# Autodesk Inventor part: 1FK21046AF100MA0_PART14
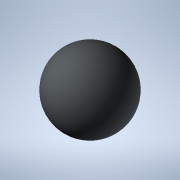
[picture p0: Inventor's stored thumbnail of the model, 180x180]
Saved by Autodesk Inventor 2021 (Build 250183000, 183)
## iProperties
Created: 2025-04
Part Number: 1FK21046AF100MA0_PART14
Material: Generic
Catalog Web Link: www.3dfindit.com
Description: -Servo synchronous motor
Document SubType Name: Modeling
Designer: psAdmin
Mass: 0.137258 g
Surface Area: 1.2868 cm^2
Volume: 0.137258 cm^3
Density: 1 g/cm^3
Appearance: PSOLRGB-212-217-219
Category: PARTsolutions
Title: 1FK21046AF100MA0_PART14
Author: Cadenas PARTsolutions
Comments: Servo synchronous motor
Sending System: PARTsolutions
Preprocessor: ST-DEVELOPER v19.3
PSOL_IDENT_0: {$CADENAS_DATA/23d-libs/siemens_ag/_cat_/4f/2b/1fk21046af100ma0.prj},216 {VTYP=3D},{NB=1FK21046AF100
PSOL_IDENT_1: MA0_PART14},{LINA=1FK21046AF100MA0_PART14},{NN=1FK21046AF100MA0_PART14},{NOPRJ=TRUE},{DATE=19.08.202
PSOL_IDENT_2: 5 14:00:37},{GEOMDATE=30.07.2025 02:01:06},{VERSION=},{LINEID=10},{WBVAR=},{WBNUMERIC=}  {NB=1FK2104
PSOL_IDENT_3: 6AF100MA0_PART14},{LINA=1FK21046AF100MA0_PART14},{KT=DUMMY},{PREVIEW=../../../_pool_/cb/72/p_d211_xx
PSOL_IDENT_4: _00434j.png},{DESCSHORT=SIMOTICS S-1FK2 HD, SINAMICS S210 3AC 400V-480V, 3.2 Nm, 3000 rpm},{DESCLONG=
PSOL_IDENT_5: SIMOTICS S-1FK2 HD servo motor M0=3.2 Nm; PN = 1 kW at nN=3000 rpm (380-480 V); PN = 0.5 kW at nN=15
PSOL_IDENT_6: 00 rpm (200-240 V); with holding brake; degree of protection IP64; cylindrical shaft D19x40mm; absol
PSOL_IDENT_7: ute encoder 22-bit + 12-bit multiturn (encoder AM22DQC); with OCC interface; plug size M17, rotatabl
PSOL_IDENT_8: e; SIMOTICS S-1FK2 servomotorfor a wide range of uses in industrial environments. SIMOTICS S‑1FK2 se
PSOL_IDENT_9: rvomotors are compact synchronous motors with a high dynamic performance that set themselves apart a
PSOL_IDENT_10: s a result of their high power density, degree of protection and overload capability. The motors are
PSOL_IDENT_11: available in two variants: as High Dynamic variant (highest dynamic performance as a result of the
PSOL_IDENT_12: low intrinsic moment of inertia for applications demanding a high dynamic performance with low moved
PSOL_IDENT_13: masses) - and as Compact variant (precise and stable closed-loop control for medium up to large mov
PSOL_IDENT_14: ed masses as a result of a medium intrinsic moment of inertia). SIMOTICSS‑1FK2 servomotors fully exp
PSOL_IDENT_15: loit their strengths in a system with the SINAMICSS210 frequency converter and simple connection usi
PSOL_IDENT_16: ng the one cable connection (OCC). Advantages include the short control and positioning times, fast
PSOL_IDENT_17: and precise correction of disturbing quantities as well as stable control with a high dynamic perfor
PSOL_IDENT_18: mance. The servo motors can be configured to address a wide range of requirements. For example with
PSOL_IDENT_19: and without holding brake, IP64 or IP65 degree of protection, singleturn or multiturn absolute encod
PSOL_IDENT_20: ers - to name just a few. Further, the servomotors are available in different shaft heights extendin
PSOL_IDENT_21: g from 20 to 100. A shaft sealing ring is available to achieve an IP65 degree of protection and for
PSOL_IDENT_22: subsequent mounting at the motor or as spare part. SIMOTICS - the optimum motor for each and every m
PSOL_IDENT_23: otion control application.},{INTNO=195125049673},{SUPPLIERALTNO=1FK2104-6AF10-0MA0},{MANUID=1FK21046
PSOL_IDENT_24: AF100MA0},{MANUNAME=Siemens},{MANUTYPEDESC=Synchronous motor 1FK2-HD 3.2 NM},{AAU732=SIMOTICS},{AAO0
PSOL_IDENT_25: 57=S-1FK2},{AAU734=SIMOTICS S-1FK2 HD servo motor M0=3.2 Nm; PN = 1 kW at nN=3000 rpm (380-480 V); P
PSOL_IDENT_26: N = 0.5 kW at nN=1500 rpm (200-240 V); with holding brake; degree of protection IP64; cylindrical sh
PSOL_IDENT_27: aft D19x40mm; absolute encoder 22-bit + 12-bit multiturn (encoder AM22DQC); with OCC interface; plug
PSOL_IDENT_28: size M17, rotatable;},{AAW338=Synchronous motor 1FK2-HD 3.2 NM},{AAO742=SIMOTICS},{AAO663=404294869
PSOL_IDENT_29: 4534},{NOCUPEROU=1},{PRICEQUANTITY=1},{QUANTITYMIN=1},{QUANTITYINT=1},{CTN=85015220},{COO=DE},{AAO67
PSOL_IDENT_30: 6=1FK2104-6AF10-0MA0},{AAO677=Siemens AG},{ORDERUNIT=C62},{CONTENTUNIT=C62}
NB: 1FK21046AF100MA0_PART14
NT: Servo synchronous motor
NBSYN: $MANUID._PART14
LINA: 1FK21046AF100MA0_PART14
CATALOG: SIEMENS
PREVIEW: ../../../_pool_/cb/72/p_d211_xx_00434j.png
DESCSHORT: SIMOTICS S-1FK2 HD, SINAMICS S210 3AC 400V-480V, 3.2 Nm, 3000 rpm
DESCLONG: SIMOTICS S-1FK2 HD servo motor M0=3.2 Nm; PN = 1 kW at nN=3000 rpm (380-480 V); PN = 0.5 kW at nN=1500 rpm (200-240 V); with holding brake; degree of protection
INTNO: 195125049673
SUPPLIERALTNO: 1FK2104-6AF10-0MA0
MANUID: 1FK21046AF100MA0
MANUNAME: Siemens
MANUTYPEDESC: Synchronous motor 1FK2-HD 3.2 NM
AAU732: SIMOTICS
AAO057: S-1FK2
AAU734: SIMOTICS S-1FK2 HD servo motor M0=3.2 Nm; PN = 1 kW at nN=3000 rpm (380-480 V); PN = 0.5 kW at nN=1500 rpm (200-240 V); with holding brake; degree of protection
AAW338: Synchronous motor 1FK2-HD 3.2 NM
AAO742: SIMOTICS
AAO663: 4042948694534.0
NOCUPEROU: 1
PRICEQUANTITY: 1
QUANTITYMIN: 1
QUANTITYINT: 1
CTN: 85015220
COO: DE
ARTICLENO: 1FK21046AF100MA0_PART14
BOMINFO: 1FK21046AF100MA0_PART14
CREATOR: CADENAS GmbH
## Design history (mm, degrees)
feature "2025_04_17_14_59_39_0177"
body "Solid1"
